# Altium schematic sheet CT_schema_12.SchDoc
size 387 x 278 mm
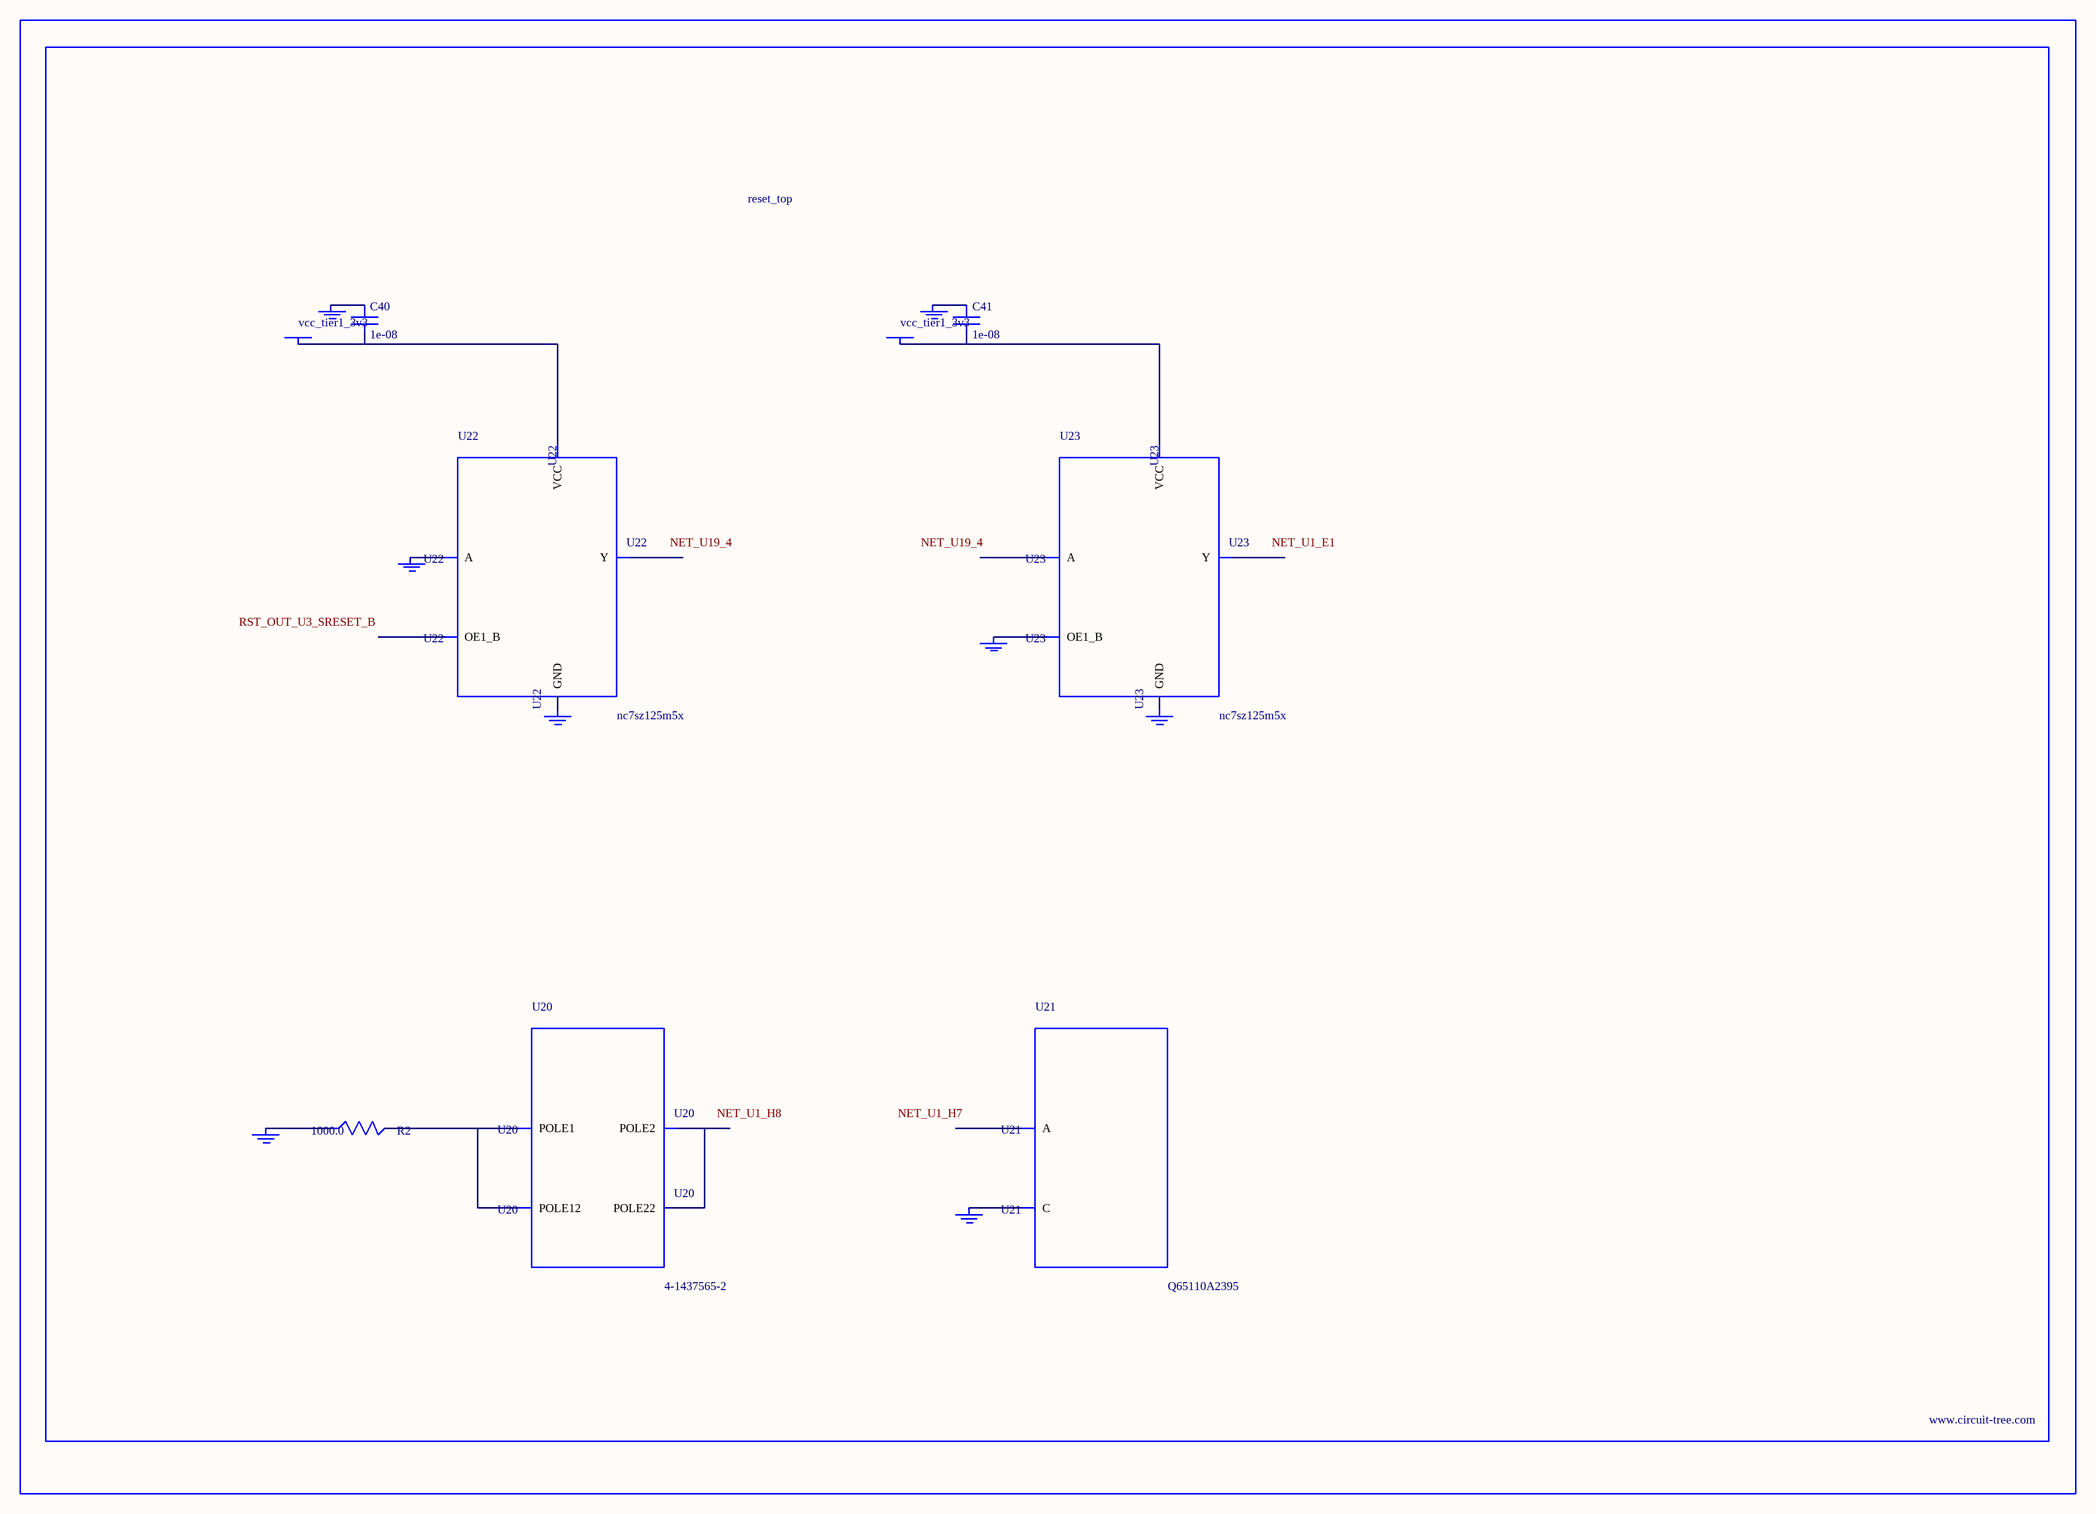
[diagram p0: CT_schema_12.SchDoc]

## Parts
BORDER11  (no value)
C40  1e-08  [C0402]
C41  1e-08  [C0402]
GND_INSTANCE_11_0  (no value)
GND_INSTANCE_11_1  (no value)
GND_INSTANCE_11_2  (no value)
GND_INSTANCE_11_3  (no value)
GND_INSTANCE_11_4  (no value)
GND_INSTANCE_11_5  (no value)
GND_INSTANCE_11_6  (no value)
GND_INSTANCE_11_7  (no value)
POWER_INSTANCE_11_0  vcc_tier1_3v3
POWER_INSTANCE_11_1  vcc_tier1_3v3
R2  1000.0  [R0603]
U20  4-1437565-2  [SW_4-1437565-2]
U21  Q65110A2395  [LGM67K-G1J2-24-Z]
U22  nc7sz125m5x  [NC7SZ125M5X]
U23  nc7sz125m5x  [NC7SZ125M5X]

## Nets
NetC40_1: C40.1 GND_INSTANCE_11_2.0(GND)
NetC40_2: C40.2 POWER_INSTANCE_11_0.0(PWR) U22.5(VCC)
NetC41_1: C41.1 GND_INSTANCE_11_5.0(GND)
NetC41_2: C41.2 POWER_INSTANCE_11_1.0(PWR) U23.5(VCC)
NetGND_INSTANCE_11_0_0: GND_INSTANCE_11_0.0(GND) R2.1
NetGND_INSTANCE_11_1_0: GND_INSTANCE_11_1.0(GND) U21.C
NetGND_INSTANCE_11_3_0: GND_INSTANCE_11_3.0(GND) U22.2(A)
NetGND_INSTANCE_11_4_0: GND_INSTANCE_11_4.0(GND) U22.3(GND)
NetGND_INSTANCE_11_6_0: GND_INSTANCE_11_6.0(GND) U23.1(OE1_B)
NetGND_INSTANCE_11_7_0: GND_INSTANCE_11_7.0(GND) U23.3(GND)
NetR2_2: R2.2 U20.1(POLE1) U20.2(POLE12)
NetU20_3: U20.3(POLE2) U20.4(POLE22)

Not connected (* = marked no-connect by the designer): U21 A; U22 1(OE1_B) 4(Y); U23 2(A) 4(Y)

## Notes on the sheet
- Labels drawn without touching a wire or pin: NET_U1_E1, NET_U1_H7, NET_U1_H8, NET_U19_4, RST_OUT_U3_SRESET_B

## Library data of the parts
BORDER11 = BORDER_PAGE11
C40 C41 = C0402C103K3RAC
GND_INSTANCE_11_0-GND_INSTANCE_11_7 = GND
POWER_INSTANCE_11_0 POWER_INSTANCE_11_1 = PWR
R2 = RC0603JR-071KL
